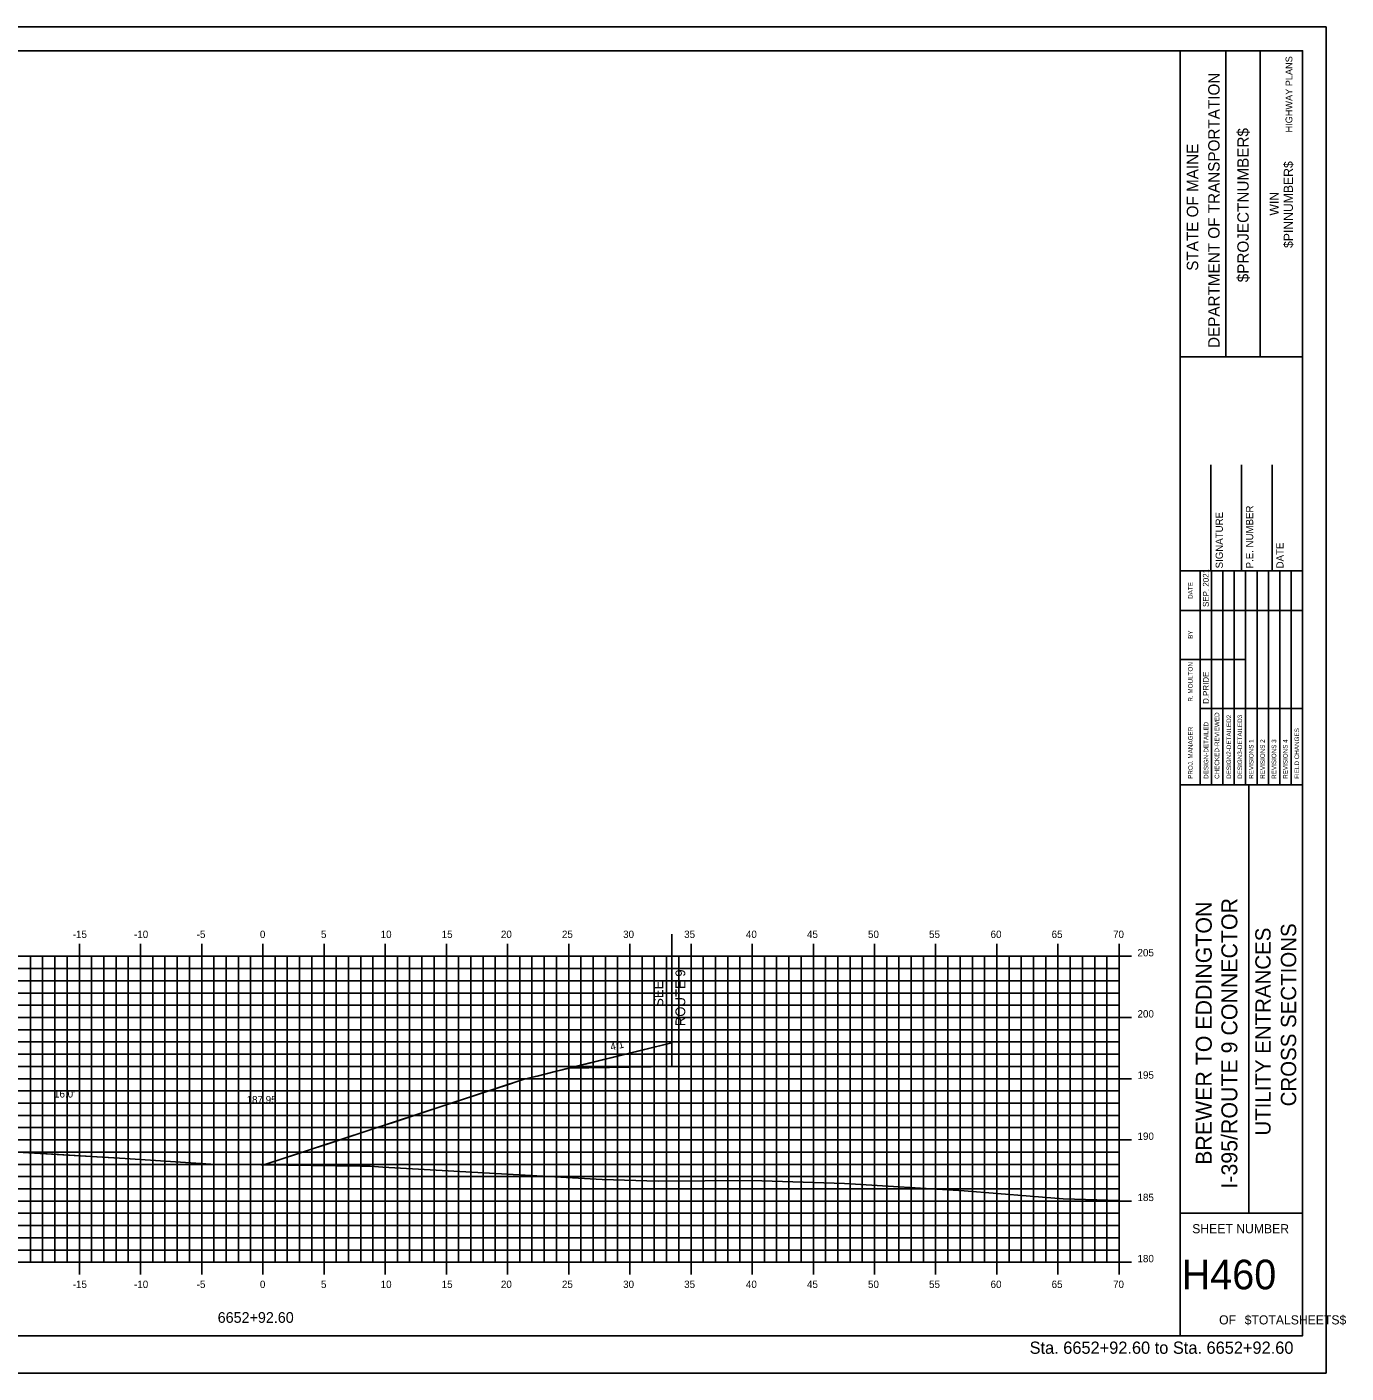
# Model space of a CAD drawing. Extents: x 1724403 to 1724575, y 458501 to 458611.
# Drawn here: x 1724467.1 to 1724574.9, y 458501.2 to 458611.2 of the extents above; entities that cross this region are included whole.
import ezdxf

# ---------------------------------------------------------------- set-up
doc = ezdxf.new("R2010")
doc.units = 0
for name, color, linetype in [('ANNOTATION', 7, 'Continuous'), ('BORDER', 7, 'Continuous'), ('D_Roadway_Centerline', 7, 'Continuous'), ('D_Roadway_Centerline_Text', 7, 'Continuous'), ('D_Roadway_Edge_Shoulder', 7, 'Continuous'), ('D_Roadway_SlopeLines', 7, 'Continuous'), ('D_Roadway_SubGrade', 7, 'Continuous'), ('D_Text_Standard', 7, 'Continuous'), ('H_V ANNOTATION', 7, 'Continuous'), ('HIGHWAY_TITLE', 7, 'Continuous'), ('MAJOR', 7, 'Continuous'), ('MINOR', 7, 'Continuous'), ('PLOT BOUNDARY', 7, 'Continuous'), ('S_Roadway_Centerline', 7, 'Continuous')]:
    doc.layers.add(name, color=color, linetype=linetype)

msp = doc.modelspace()

# ---------------------------------------------------------------- linework, layer by layer
at = {"layer": 'ANNOTATION'}
msp.add_lwpolyline([(1724486.39, 458518.21), (1724482.14, 458518.26), (1724475.14, 458518.73), (1724467.39, 458519.18)], dxfattribs=at)
at = {"layer": 'BORDER'}
for p, q in [((1724561.39, 458504.25), (1724561.39, 458609.25)), ((1724565.12, 458584.25), (1724565.12, 458609.25)), ((1724567.92, 458584.25), (1724567.92, 458609.25)), ((1724561.39, 458584.25), (1724571.39, 458584.25)), ((1724563.89, 458566.76), (1724563.89, 458575.4)), ((1724566.39, 458566.76), (1724566.39, 458575.4)), ((1724568.89, 458566.76), (1724568.89, 458575.4)), ((1724561.39, 458566.76), (1724571.39, 458566.76)), ((1724561.39, 458549.26), (1724571.39, 458549.26)), ((1724566.98, 458514.26), (1724566.98, 458549.26)), ((1724561.39, 458514.26), (1724571.39, 458514.26))]:
    msp.add_line(p, q, dxfattribs=at)
msp.add_lwpolyline([(1724411.39, 458504.25), (1724571.39, 458504.25), (1724571.39, 458609.25), (1724411.39, 458609.25)], close=True, dxfattribs=at)
for points in [[(1724563.01, 458563.51), (1724563.01, 458566.76)], [(1724563.01, 458549.26), (1724563.01, 458566.05)], [(1724563.94, 458549.26), (1724563.94, 458566.76)], [(1724564.87, 458566.76), (1724564.87, 458549.26)], [(1724565.8, 458549.26), (1724565.8, 458566.76)], [(1724566.73, 458549.26), (1724566.73, 458566.76)], [(1724567.67, 458549.26), (1724567.67, 458566.76)], [(1724568.6, 458549.26), (1724568.6, 458566.76)], [(1724569.53, 458549.26), (1724569.53, 458566.76)], [(1724570.46, 458549.26), (1724570.46, 458566.76)], [(1724561.39, 458563.51), (1724571.39, 458563.51)], [(1724561.39, 458559.51), (1724563.01, 458559.51)], [(1724563.01, 458559.51), (1724566.73, 458559.51)], [(1724563.01, 458555.51), (1724571.39, 458555.51)]]:
    msp.add_lwpolyline(points, dxfattribs=at)
at = {"layer": 'D_Roadway_Centerline'}
msp.add_lwpolyline([(1724486.48, 458518.21), (1724489.31, 458519.14), (1724489.47, 458519.19), (1724490.46, 458519.52), (1724491.82, 458519.96), (1724495.81, 458521.28), (1724497.04, 458521.68), (1724498.26, 458522.08), (1724501.05, 458523.01), (1724502.31, 458523.42), (1724505.71, 458524.54), (1724506.05, 458524.65), (1724507.68, 458525.19), (1724508.33, 458525.35), (1724508.81, 458525.47), (1724510.28, 458525.83), (1724511.36, 458526.1), (1724512.92, 458526.48), (1724513.85, 458526.71), (1724514.73, 458526.93), (1724515.31, 458527.07), (1724517.24, 458527.55), (1724519.82, 458528.19)], dxfattribs=at)
at = {"layer": 'D_Roadway_Edge_Shoulder'}
msp.add_line((1724519.82, 458528.19), (1724519.82, 458527.94), dxfattribs=at)
msp.add_line((1724519.82, 458528.19), (1724519.82, 458527.94), dxfattribs=at)
at = {"layer": 'D_Roadway_SlopeLines'}
for points in [[(1724519.82, 458528.19), (1724507.68, 458525.19), (1724486.48, 458518.21)], [(1724519.82, 458528.19), (1724507.68, 458525.19), (1724486.48, 458518.21)], [(1724519.82, 458528.19), (1724507.68, 458525.19), (1724486.48, 458518.21)], [(1724519.82, 458528.19), (1724507.68, 458525.19), (1724486.48, 458518.21)], [(1724519.82, 458528.19), (1724507.68, 458525.19), (1724486.48, 458518.21)], [(1724519.82, 458528.19), (1724507.68, 458525.19), (1724486.48, 458518.21)], [(1724519.82, 458528.19), (1724507.68, 458525.19)], [(1724519.82, 458528.19), (1724507.68, 458525.19)], [(1724519.82, 458528.19), (1724511.36, 458526.1)], [(1724486.39, 458518.21), (1724486.49, 458518.21)]]:
    msp.add_lwpolyline(points, dxfattribs=at)
at = {"layer": 'D_Roadway_SubGrade'}
msp.add_line((1724519.82, 458537.05), (1724519.82, 458526.26), dxfattribs=at)
for points in [[(1724519.82, 458526.26), (1724511.36, 458526.1), (1724519.82, 458528.19), (1724519.82, 458527.94)], [(1724519.82, 458527.94), (1724519.82, 458528.19), (1724511.36, 458526.1), (1724519.82, 458526.26)]]:
    msp.add_lwpolyline(points, dxfattribs=at)
at = {"layer": 'MAJOR'}
for p, q in [((1724471.39, 458536.26), (1724471.39, 458535.25)), ((1724476.39, 458536.26), (1724476.39, 458535.25)), ((1724481.39, 458536.26), (1724481.39, 458535.25)), ((1724486.39, 458536.26), (1724486.39, 458535.25)), ((1724491.39, 458536.26), (1724491.39, 458535.25)), ((1724496.39, 458536.26), (1724496.39, 458535.25)), ((1724501.39, 458536.26), (1724501.39, 458535.25)), ((1724506.39, 458536.26), (1724506.39, 458535.25)), ((1724511.39, 458536.26), (1724511.39, 458535.25)), ((1724516.39, 458536.26), (1724516.39, 458535.25)), ((1724521.39, 458536.26), (1724521.39, 458535.25)), ((1724526.39, 458536.26), (1724526.39, 458535.25)), ((1724531.39, 458536.26), (1724531.39, 458535.25)), ((1724536.39, 458536.26), (1724536.39, 458535.25)), ((1724541.39, 458536.26), (1724541.39, 458535.25)), ((1724546.39, 458536.26), (1724546.39, 458535.25)), ((1724551.39, 458536.26), (1724551.39, 458535.25)), ((1724556.39, 458536.26), (1724556.39, 458535.25)), ((1724416.39, 458535.25), (1724556.39, 458535.25)), ((1724416.39, 458535.25), (1724556.39, 458535.25)), ((1724471.39, 458510.25), (1724471.39, 458535.25)), ((1724476.39, 458510.25), (1724476.39, 458535.25)), ((1724481.39, 458510.25), (1724481.39, 458535.25)), ((1724486.39, 458510.25), (1724486.39, 458535.25)), ((1724491.39, 458510.25), (1724491.39, 458535.25)), ((1724496.39, 458510.25), (1724496.39, 458535.25)), ((1724501.39, 458510.25), (1724501.39, 458535.25)), ((1724506.39, 458510.25), (1724506.39, 458535.25)), ((1724511.39, 458510.25), (1724511.39, 458535.25)), ((1724516.39, 458510.25), (1724516.39, 458535.25)), ((1724521.39, 458510.25), (1724521.39, 458535.25)), ((1724526.39, 458510.25), (1724526.39, 458535.25)), ((1724531.39, 458510.25), (1724531.39, 458535.25)), ((1724536.39, 458510.25), (1724536.39, 458535.25)), ((1724541.39, 458510.25), (1724541.39, 458535.25)), ((1724546.39, 458510.25), (1724546.39, 458535.25)), ((1724551.39, 458510.25), (1724551.39, 458535.25)), ((1724557.39, 458535.25), (1724555.39, 458535.25)), ((1724556.39, 458510.25), (1724556.39, 458535.25)), ((1724556.39, 458510.25), (1724556.39, 458535.25)), ((1724416.39, 458530.25), (1724556.39, 458530.25)), ((1724557.39, 458530.25), (1724555.39, 458530.25)), ((1724416.39, 458525.25), (1724556.39, 458525.25)), ((1724557.39, 458525.25), (1724555.39, 458525.25)), ((1724416.39, 458520.25), (1724556.39, 458520.25)), ((1724557.39, 458520.25), (1724555.39, 458520.25)), ((1724416.39, 458515.25), (1724556.39, 458515.25)), ((1724557.39, 458515.25), (1724555.39, 458515.25)), ((1724416.39, 458510.25), (1724556.39, 458510.25)), ((1724416.39, 458510.25), (1724556.39, 458510.25)), ((1724471.39, 458509.25), (1724471.39, 458510.25)), ((1724476.39, 458509.25), (1724476.39, 458510.25)), ((1724481.39, 458509.25), (1724481.39, 458510.25)), ((1724486.39, 458509.25), (1724486.39, 458510.25)), ((1724491.39, 458509.25), (1724491.39, 458510.25)), ((1724496.39, 458509.25), (1724496.39, 458510.25)), ((1724501.39, 458509.25), (1724501.39, 458510.25)), ((1724506.39, 458509.25), (1724506.39, 458510.25)), ((1724511.39, 458509.25), (1724511.39, 458510.25)), ((1724516.39, 458509.25), (1724516.39, 458510.25)), ((1724521.39, 458509.25), (1724521.39, 458510.25)), ((1724526.39, 458509.25), (1724526.39, 458510.25)), ((1724531.39, 458509.25), (1724531.39, 458510.25)), ((1724536.39, 458509.25), (1724536.39, 458510.25)), ((1724541.39, 458509.25), (1724541.39, 458510.25)), ((1724546.39, 458509.25), (1724546.39, 458510.25)), ((1724551.39, 458509.25), (1724551.39, 458510.25)), ((1724557.39, 458510.25), (1724555.39, 458510.25)), ((1724556.39, 458509.25), (1724556.39, 458510.25))]:
    msp.add_line(p, q, dxfattribs=at)
at = {"layer": 'MINOR'}
for p, q in [((1724467.39, 458510.25), (1724467.39, 458535.25)), ((1724468.39, 458510.25), (1724468.39, 458535.25)), ((1724469.39, 458510.25), (1724469.39, 458535.25)), ((1724470.39, 458510.25), (1724470.39, 458535.25)), ((1724472.39, 458510.25), (1724472.39, 458535.25)), ((1724473.39, 458510.25), (1724473.39, 458535.25)), ((1724474.39, 458510.25), (1724474.39, 458535.25)), ((1724475.39, 458510.25), (1724475.39, 458535.25)), ((1724477.39, 458510.25), (1724477.39, 458535.25)), ((1724478.39, 458510.25), (1724478.39, 458535.25)), ((1724479.39, 458510.25), (1724479.39, 458535.25)), ((1724480.39, 458510.25), (1724480.39, 458535.25)), ((1724482.39, 458510.25), (1724482.39, 458535.25)), ((1724483.39, 458510.25), (1724483.39, 458535.25)), ((1724484.39, 458510.25), (1724484.39, 458535.25)), ((1724485.39, 458510.25), (1724485.39, 458535.25)), ((1724487.39, 458510.25), (1724487.39, 458535.25)), ((1724488.39, 458510.25), (1724488.39, 458535.25)), ((1724489.39, 458510.25), (1724489.39, 458535.25)), ((1724490.39, 458510.25), (1724490.39, 458535.25)), ((1724492.39, 458510.25), (1724492.39, 458535.25)), ((1724493.39, 458510.25), (1724493.39, 458535.25)), ((1724494.39, 458510.25), (1724494.39, 458535.25)), ((1724495.39, 458510.25), (1724495.39, 458535.25)), ((1724497.39, 458510.25), (1724497.39, 458535.25)), ((1724498.39, 458510.25), (1724498.39, 458535.25)), ((1724499.39, 458510.25), (1724499.39, 458535.25)), ((1724500.39, 458510.25), (1724500.39, 458535.25)), ((1724502.39, 458510.25), (1724502.39, 458535.25)), ((1724503.39, 458510.25), (1724503.39, 458535.25)), ((1724504.39, 458510.25), (1724504.39, 458535.25)), ((1724505.39, 458510.25), (1724505.39, 458535.25)), ((1724507.39, 458510.25), (1724507.39, 458535.25)), ((1724508.39, 458510.25), (1724508.39, 458535.25)), ((1724509.39, 458510.25), (1724509.39, 458535.25)), ((1724510.39, 458510.25), (1724510.39, 458535.25)), ((1724512.39, 458510.25), (1724512.39, 458535.25)), ((1724513.39, 458510.25), (1724513.39, 458535.25)), ((1724514.39, 458510.25), (1724514.39, 458535.25)), ((1724515.39, 458510.25), (1724515.39, 458535.25)), ((1724517.39, 458510.25), (1724517.39, 458535.25)), ((1724518.39, 458510.25), (1724518.39, 458535.25)), ((1724519.39, 458510.25), (1724519.39, 458535.25)), ((1724520.39, 458510.25), (1724520.39, 458535.25)), ((1724522.39, 458510.25), (1724522.39, 458535.25)), ((1724523.39, 458510.25), (1724523.39, 458535.25)), ((1724524.39, 458510.25), (1724524.39, 458535.25)), ((1724525.39, 458510.25), (1724525.39, 458535.25)), ((1724527.39, 458510.25), (1724527.39, 458535.25)), ((1724528.39, 458510.25), (1724528.39, 458535.25)), ((1724529.39, 458510.25), (1724529.39, 458535.25)), ((1724530.39, 458510.25), (1724530.39, 458535.25)), ((1724532.39, 458510.25), (1724532.39, 458535.25)), ((1724533.39, 458510.25), (1724533.39, 458535.25)), ((1724534.39, 458510.25), (1724534.39, 458535.25)), ((1724535.39, 458510.25), (1724535.39, 458535.25)), ((1724537.39, 458510.25), (1724537.39, 458535.25)), ((1724538.39, 458510.25), (1724538.39, 458535.25)), ((1724539.39, 458510.25), (1724539.39, 458535.25)), ((1724540.39, 458510.25), (1724540.39, 458535.25)), ((1724542.39, 458510.25), (1724542.39, 458535.25)), ((1724543.39, 458510.25), (1724543.39, 458535.25)), ((1724544.39, 458510.25), (1724544.39, 458535.25)), ((1724545.39, 458510.25), (1724545.39, 458535.25)), ((1724547.39, 458510.25), (1724547.39, 458535.25)), ((1724548.39, 458510.25), (1724548.39, 458535.25)), ((1724549.39, 458510.25), (1724549.39, 458535.25)), ((1724550.39, 458510.25), (1724550.39, 458535.25)), ((1724552.39, 458510.25), (1724552.39, 458535.25)), ((1724553.39, 458510.25), (1724553.39, 458535.25)), ((1724554.39, 458510.25), (1724554.39, 458535.25)), ((1724555.39, 458510.25), (1724555.39, 458535.25)), ((1724416.39, 458534.25), (1724556.39, 458534.25)), ((1724556.39, 458534.25), (1724555.39, 458534.25)), ((1724416.39, 458533.25), (1724556.39, 458533.25)), ((1724556.39, 458533.25), (1724555.39, 458533.25)), ((1724416.39, 458532.25), (1724556.39, 458532.25)), ((1724556.39, 458532.25), (1724555.39, 458532.25)), ((1724416.39, 458531.25), (1724556.39, 458531.25)), ((1724556.39, 458531.25), (1724555.39, 458531.25)), ((1724416.39, 458529.25), (1724556.39, 458529.25)), ((1724556.39, 458529.25), (1724555.39, 458529.25)), ((1724416.39, 458528.25), (1724556.39, 458528.25)), ((1724556.39, 458528.25), (1724555.39, 458528.25)), ((1724416.39, 458527.25), (1724556.39, 458527.25)), ((1724416.39, 458526.25), (1724556.39, 458526.25)), ((1724556.39, 458527.25), (1724555.39, 458527.25)), ((1724556.39, 458526.25), (1724555.39, 458526.25)), ((1724416.39, 458524.25), (1724556.39, 458524.25)), ((1724556.39, 458524.25), (1724555.39, 458524.25)), ((1724416.39, 458523.25), (1724556.39, 458523.25)), ((1724556.39, 458523.25), (1724555.39, 458523.25)), ((1724416.39, 458522.25), (1724556.39, 458522.25)), ((1724556.39, 458522.25), (1724555.39, 458522.25)), ((1724416.39, 458521.25), (1724556.39, 458521.25)), ((1724556.39, 458521.25), (1724555.39, 458521.25)), ((1724416.39, 458519.25), (1724556.39, 458519.25)), ((1724556.39, 458519.25), (1724555.39, 458519.25)), ((1724416.39, 458518.25), (1724556.39, 458518.25)), ((1724556.39, 458518.25), (1724555.39, 458518.25)), ((1724416.39, 458517.25), (1724556.39, 458517.25)), ((1724556.39, 458517.25), (1724555.39, 458517.25)), ((1724416.39, 458516.25), (1724556.39, 458516.25)), ((1724556.39, 458516.25), (1724555.39, 458516.25)), ((1724416.39, 458514.25), (1724556.39, 458514.25)), ((1724556.39, 458514.25), (1724555.39, 458514.25)), ((1724416.39, 458513.25), (1724556.39, 458513.25)), ((1724556.39, 458513.25), (1724555.39, 458513.25)), ((1724416.39, 458512.25), (1724556.39, 458512.25)), ((1724556.39, 458512.25), (1724555.39, 458512.25)), ((1724416.39, 458511.25), (1724556.39, 458511.25)), ((1724556.39, 458511.25), (1724555.39, 458511.25))]:
    msp.add_line(p, q, dxfattribs=at)
at = {"layer": 'PLOT BOUNDARY'}
msp.add_lwpolyline([(1724403.3, 458501.2), (1724573.3, 458501.2), (1724573.3, 458611.2), (1724403.3, 458611.2)], close=True, dxfattribs=at)
at = {"layer": 'S_Roadway_Centerline'}
msp.add_lwpolyline([(1724416.39, 458519.45), (1724418.16, 458519.44), (1724428.69, 458519.29), (1724437.6, 458519.27), (1724448.18, 458519.57), (1724458.11, 458519.62), (1724462.15, 458519.48), (1724475.14, 458518.73), (1724482.14, 458518.26), (1724494.46, 458518.11), (1724495.17, 458518.09), (1724496.19, 458518.03), (1724514.14, 458517.02), (1724518.7, 458516.87), (1724526.33, 458516.92), (1724533.95, 458516.69), (1724543.73, 458516.08), (1724551.8, 458515.43), (1724556.39, 458515.3)], dxfattribs=at)

# ---------------------------------------------------------------- texts
at = {"layer": 'ANNOTATION'}
for s, height, rotation, p in [('ROUTE 9', 0.8, 90, (1724520.92, 458529.54)), ('SEE', 0.8, 90, (1724519.12, 458531.12)), ('4:1', 0.6, 13.6162, (1724514.87, 458527.54))]:
    msp.add_text(s, height=height, rotation=rotation, dxfattribs=at).set_placement(p)
at = {"layer": 'BORDER'}
for s, height, p in [('DEPARTMENT OF TRANSPORTATION', 0.9318, (1724564.6, 458584.96)), ('$PROJECTNUMBER$', 0.9318, (1724566.98, 458590.33)), ('STATE OF MAINE', 0.9318, (1724562.85, 458591.27)), ('$PINNUMBER$', 0.7453, (1724570.59, 458593.13)), ('WIN', 0.745, (1724569.43, 458595.78)), ('SIGNATURE', 0.591, (1724564.87, 458566.95)), ('P.E. NUMBER', 0.5906, (1724567.35, 458566.95)), ('DATE', 0.591, (1724569.83, 458566.95)), ('SEP. 2021', 0.485, (1724563.72, 458563.8)), ('DATE', 0.371, (1724562.4, 458564.46)), ('BY', 0.371, (1724562.4, 458561.19)), ('R. MOULTON', 0.373, (1724562.4, 458556.06)), ('D.PRIDE', 0.485, (1724563.72, 458555.88)), ('CHECKED-REVIEWED', 0.3727, (1724564.57, 458549.75)), ('PROJ. MANAGER', 0.3727, (1724562.4, 458549.75)), ('DESIGN-DETAILED', 0.3727, (1724563.68, 458549.75)), ('DESIGN2-DETAILED2', 0.3727, (1724565.54, 458549.75)), ('DESIGN3-DETAILED3', 0.3727, (1724566.44, 458549.75)), ('FIELD CHANGES', 0.3727, (1724571.1, 458549.75)), ('REVISIONS 1', 0.3727, (1724567.37, 458549.75)), ('REVISIONS 2', 0.3727, (1724568.3, 458549.75)), ('REVISIONS 3', 0.3727, (1724569.23, 458549.75)), ('REVISIONS 4', 0.3727, (1724570.16, 458549.75)), ('UTILITY ENTRANCES', 1.25, (1724568.77, 458520.6)), ('CROSS SECTIONS', 1.25, (1724570.86, 458522.99))]:
    msp.add_text(s, height=height, rotation=90, dxfattribs=at).set_placement(p)
for s, height, p in [('SHEET NUMBER', 0.7453, (1724562.36, 458512.62)), ('H460', 2.419, (1724561.5, 458508.04)), ('OF', 0.745, (1724564.56, 458505.17)), ('$TOTALSHEETS$', 0.7453, (1724566.65, 458505.17))]:
    msp.add_text(s, height=height, dxfattribs=at).set_placement(p)
at = {"layer": 'D_Roadway_Centerline_Text'}
msp.add_text('187.95', height=0.6, dxfattribs=at).set_placement((1724485.06, 458523.24))
at = {"layer": 'D_Text_Standard'}
msp.add_text("16.0'", height=0.6, dxfattribs=at).set_placement((1724469.32, 458523.71))
at = {"layer": 'H_V ANNOTATION'}
for s, height, p in [('-15', 0.6, (1724470.85, 458536.75)), ('-10', 0.6, (1724475.86, 458536.75)), ('-5', 0.6, (1724480.98, 458536.75)), ('0', 0.6, (1724486.15, 458536.75)), ('5', 0.6, (1724491.14, 458536.75)), ('10', 0.6, (1724496.02, 458536.75)), ('15', 0.6, (1724501.01, 458536.75)), ('20', 0.6, (1724505.85, 458536.75)), ('25', 0.6, (1724510.84, 458536.75)), ('30', 0.6, (1724515.84, 458536.75)), ('35', 0.6, (1724520.83, 458536.75)), ('40', 0.6, (1724525.88, 458536.75)), ('45', 0.6, (1724530.87, 458536.75)), ('50', 0.6, (1724535.86, 458536.75)), ('55', 0.6, (1724540.85, 458536.75)), ('60', 0.6, (1724545.88, 458536.75)), ('65', 0.6, (1724550.87, 458536.75)), ('70', 0.6, (1724555.89, 458536.75)), ('205', 0.6, (1724557.89, 458535.25)), ('200', 0.6, (1724557.89, 458530.25)), ('195', 0.6, (1724557.89, 458525.25)), ('190', 0.6, (1724557.89, 458520.25)), ('185', 0.6, (1724557.89, 458515.25)), ('180', 0.6, (1724557.89, 458510.25)), ('-15', 0.6, (1724470.85, 458508.15)), ('-10', 0.6, (1724475.86, 458508.15)), ('-5', 0.6, (1724480.98, 458508.15)), ('0', 0.6, (1724486.15, 458508.15)), ('5', 0.6, (1724491.14, 458508.15)), ('10', 0.6, (1724496.02, 458508.15)), ('15', 0.6, (1724501.01, 458508.15)), ('20', 0.6, (1724505.85, 458508.15)), ('25', 0.6, (1724510.84, 458508.15)), ('30', 0.6, (1724515.84, 458508.15)), ('35', 0.6, (1724520.83, 458508.15)), ('40', 0.6, (1724525.88, 458508.15)), ('45', 0.6, (1724530.87, 458508.15)), ('50', 0.6, (1724535.86, 458508.15)), ('55', 0.6, (1724540.85, 458508.15)), ('60', 0.6, (1724545.88, 458508.15)), ('65', 0.6, (1724550.87, 458508.15)), ('70', 0.6, (1724555.89, 458508.15)), ('6652+92.60', 0.875, (1724482.7, 458505.3)), ('Sta. 6652+92.60 to Sta. 6652+92.60', 1.0002, (1724549.07, 458502.77))]:
    msp.add_text(s, height=height, dxfattribs=at).set_placement(p)
at = {"layer": 'HIGHWAY_TITLE'}
for s, height, p in [('HIGHWAY PLANS', 0.559, (1724570.55, 458602.57)), ('BREWER TO EDDINGTON', 1.3043, (1724563.96, 458518.21)), ('I-395/ROUTE 9 CONNECTOR', 1.3043, (1724566.05, 458516.27))]:
    msp.add_text(s, height=height, rotation=90, dxfattribs=at).set_placement(p)

doc.saveas('drawing.dxf')
